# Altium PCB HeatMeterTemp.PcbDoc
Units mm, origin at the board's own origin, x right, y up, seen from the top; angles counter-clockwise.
Board outline 51.56 x 33.02 mm, 2 copper layers (Top Layer, Bottom Layer), stack 0.979 mm thick; 60 components, 38 nets, 163 pads, 77 vias.
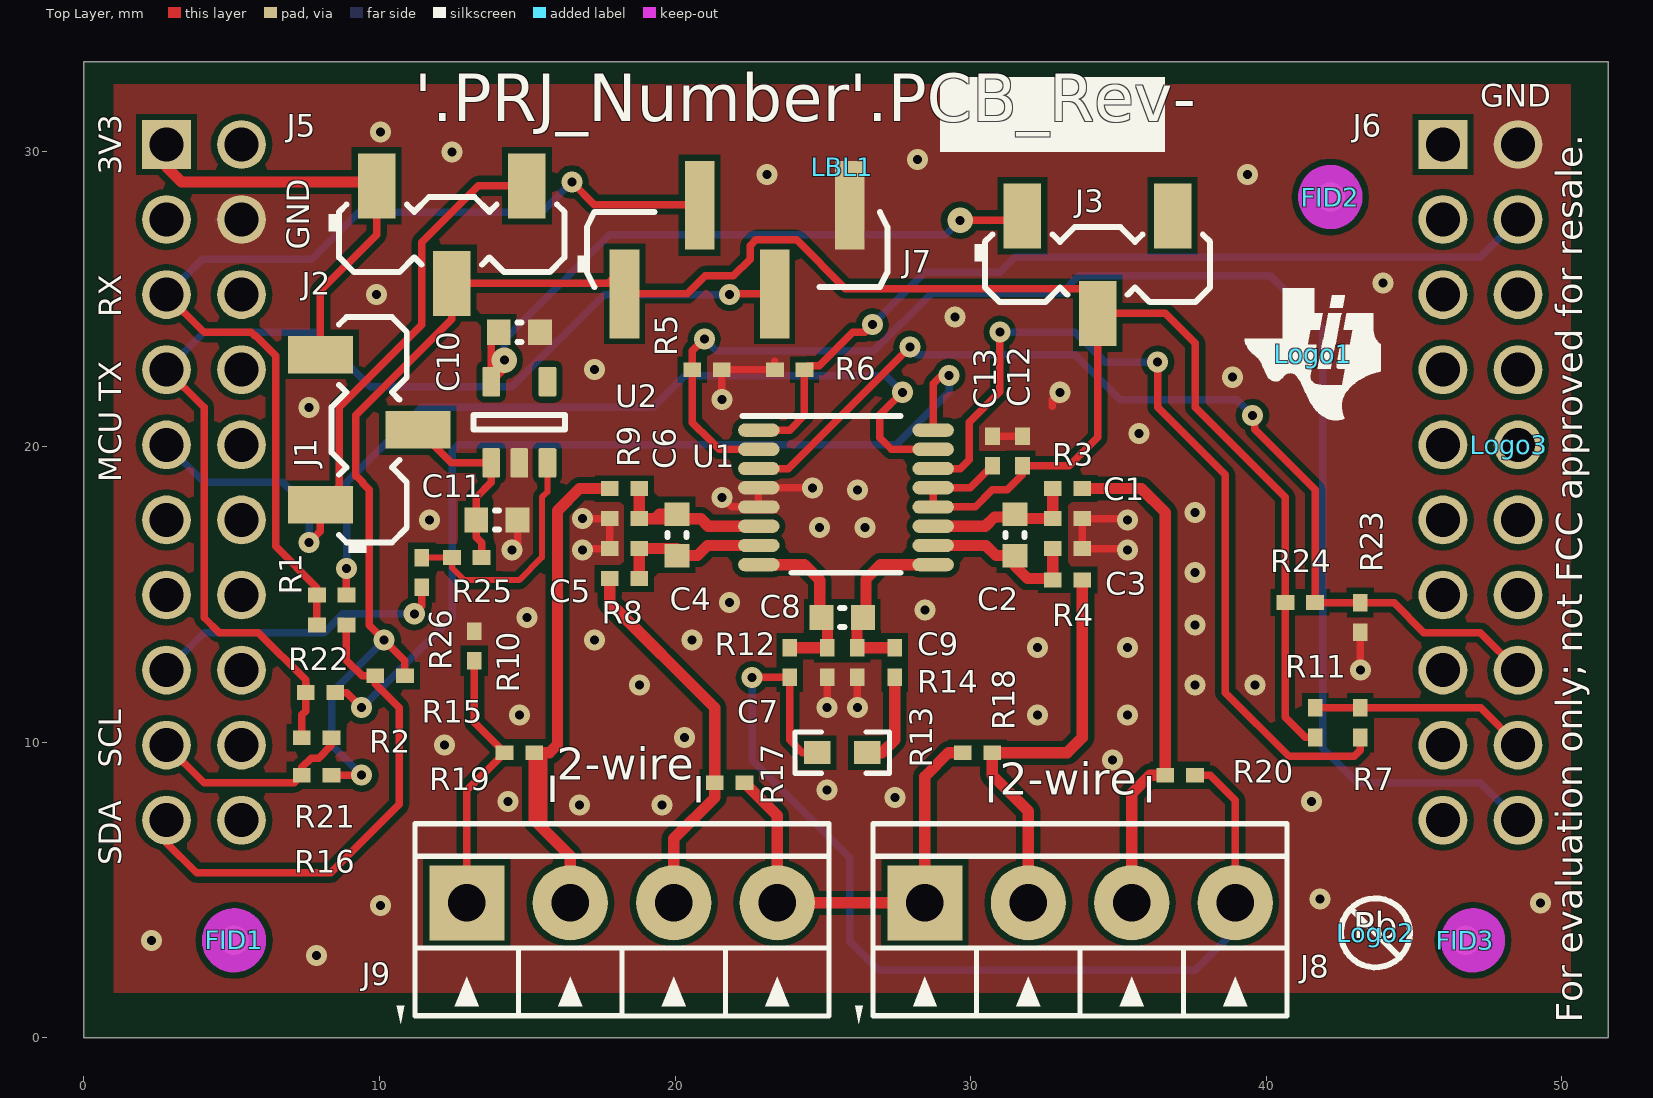
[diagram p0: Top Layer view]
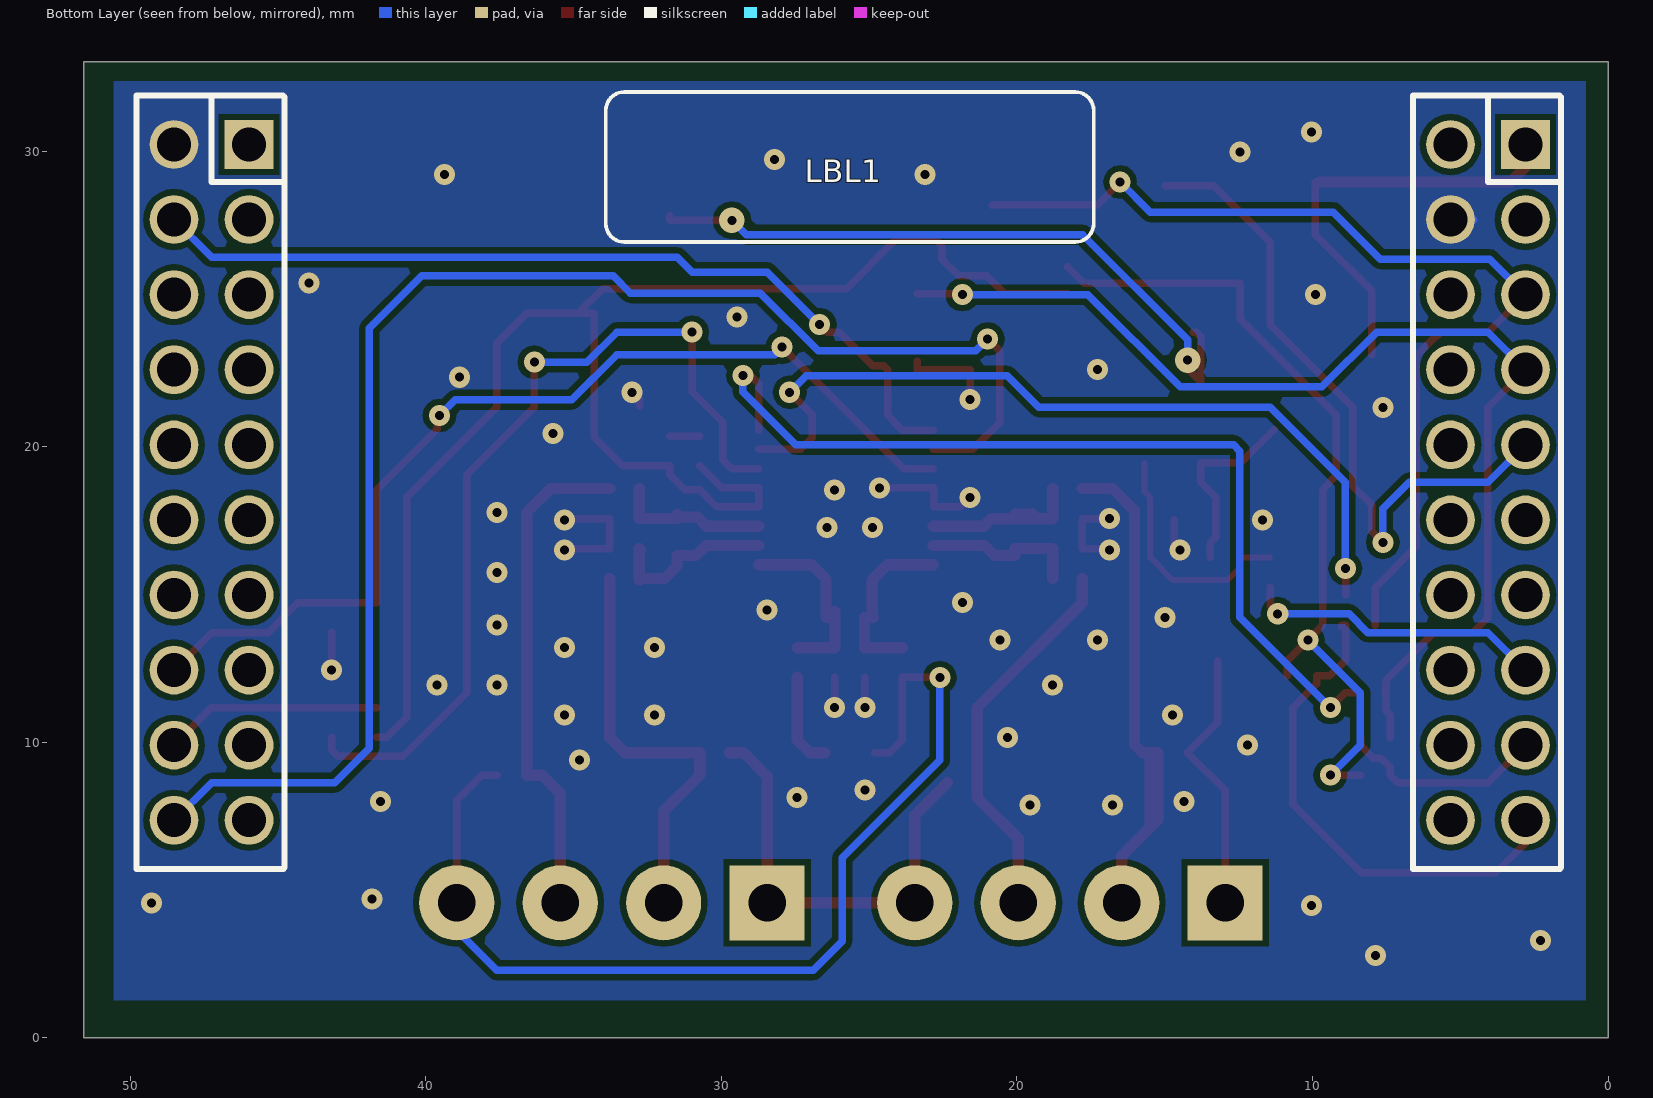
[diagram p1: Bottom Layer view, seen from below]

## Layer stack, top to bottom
Top Solder: solder mask 0.0102, Solder Resist, Dk 3.5
Top Layer: signal copper 0.0356
Dielectric1: core 0.908, FR-4, Dk 4.8
Bottom Layer: signal copper 0.0356
Bottom Solder: solder mask 0.0102, Solder Resist, Dk 3.5

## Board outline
0,0 51.562,0 51.562,33.02 0,33.02

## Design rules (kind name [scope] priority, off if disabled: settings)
AcuteAngle [All] p1: minimum=4.50000000000000E+0001 checktracksonly=FALSE
AssemblyTestPointUsage [All] p1: valid=2
BoardOutlineClearance BoardOutlineClearance_MountingHoles [OnCopper and InComponentClass('Mounting Holes')] p1: gap=1.016 ignorepadtopadclearanceinfootprint=FALSE except(0.762: Arc-OutlineEdge Track-OutlineEdge SMDPad-OutlineEdge)
BoardOutlineClearance BoardOutlineClearance_Poly [OnCopper and IsPoly] p2: gap=0.635 ignorepadtopadclearanceinfootprint=FALSE
BoardOutlineClearance [OnCopper and Not InComponentClass('Logo') and not InComponentClass('FiducialMark') and not InRegion(1000,500,4000,800) and not InPoly] p3: gap=1.905 ignorepadtopadclearanceinfootprint=FALSE
Clearance Clearance_Keepouts [((IsTrack Or IsArc) And Not InPoly) And IsFree and IsKeepOut vs ((IsTrack Or IsArc) And Not InPoly) And IsFree and IsKeepOut] p1: gap=0 ignorepadtopadclearanceinfootprint=FALSE
Clearance Clearance_Poly [InPolygon] p2: gap=0.203 ignorepadtopadclearanceinfootprint=FALSE except(0: Arc-Hole Track-Hole SMDPad-Hole THPad-Hole Via-Hole Fill-Hole Poly-Hole Region-Hole Text-Hole)
Clearance [All] p3: gap=0.2 ignorepadtopadclearanceinfootprint=FALSE except(0: Arc-Hole Track-Hole SMDPad-Hole THPad-Hole Via-Hole Fill-Hole Poly-Hole Region-Hole Text-Hole; 0.15: Arc-Via Track-Via SMDPad-Via THPad-Via Via-Via)
ComponentClearance ComponentClearance_MountingHoles_FiducialMarks [InComponentClass('Mounting Holes') vs InComponentClass('FiducialMark')] p1: gap=1.27 collisioncheckmode=3 verticalgap=0.254 showdistances=FALSE
ComponentClearance ComponentClearance_Shunt [InComponentClass('Header') vs InComponentClass('Shunt')] p2: gap=0 collisioncheckmode=3 verticalgap=0 showdistances=FALSE
ComponentClearance ComponentClearance_Logo [InComponentClass('Logo')] p3: gap=1.27 collisioncheckmode=3 verticalgap=0.254 showdistances=FALSE
ComponentClearance ComponentClearance_ScrewToNut [(HasFootprint('NY PMS 440 0025 PH')) vs (HasFootprint('Keystone_1902C'))] p4: gap=0.127 collisioncheckmode=3 verticalgap=0.254 showdistances=FALSE
ComponentClearance ComponentClearance_MountingHoles [InComponentClass('Mounting Holes')] p5: gap=6.35 collisioncheckmode=3 verticalgap=2540 showdistances=FALSE
ComponentClearance ComponentClearance_SmallPassives [HasFootprint('0201*') or HasFootprint('0402*') or HasFootprint('0508') or HasFootprint('0603*') or HasFootprint('0612') or HasFootprint('0805*') or HasFootprint('0815*') or HasFootprint('0830*') or HasFootprint('1206*') or HasFootprint('1210*') or HasFootprint('1808*') or HasFootprint('1812*') or HasFootprint('1825*') or HasFootprint('2010*') or HasFootprint('2220*') or HasFootprint('2225*') or HasFootprint('2512*') or HasFootprint('2728*') or HasFootprint('3518*') vs HasFootprint('0201*') or HasFootprint('0402*') or HasFootprint('0508') or HasFootprint('0603*') or HasFootprint('0612') or HasFootprint('0805*') or HasFootprint('0815*') or HasFootprint('0830*') or HasFootprint('1206*') or HasFootprint('1210*') or HasFootprint('1808*') or HasFootprint('1812*') or HasFootprint('1825*') or HasFootprint('2010*') or HasFootprint('2220*') or HasFootprint('2225*') or HasFootprint('2512*') or HasFootprint('2728*') or HasFootprint('3518*')] p6: gap=0.38 collisioncheckmode=3 verticalgap=0.254 showdistances=FALSE
ComponentClearance ComponentClearance_THtoSMT [IsThruComponent vs IsSMTComponent] p7: gap=1.016 collisioncheckmode=3 verticalgap=0.762 showdistances=FALSE
ComponentClearance ComponentClearance_THtoTH [IsThruComponent vs IsThruComponent] p8: gap=0.762 collisioncheckmode=3 verticalgap=0.762 showdistances=FALSE
ComponentClearance [All] p9: gap=0.762 collisioncheckmode=3 verticalgap=0.254 showdistances=FALSE
DiffPairsRouting [All] p1: maxlimit=2.54 minlimit=0.254 mostfreqgap=0.254 toplayer_minwidth=0.381 toplayer_maxwidth=0.381 toplayer_prefwidth=0.381 bottomlayer_minwidth=0.381 bottomlayer_maxwidth=0.381 bottomlayer_prefwidth=0.381 maxuncoupledlength=25.4
FabricationTestPointUsage TestPointUsage [All] p1: valid=2 allowmultiple=FALSE
FabricationTestpoint Testpoint [All] p1: side=3 testpointundercomponent=TRUE minsize=1.016 maxsize=2.54 preferedsize=1.524 minholesize=0 maxholesize=1.016 preferedholesize=0.813 testpointgrid=0.025 allowsidetop=TRUE allowsidebottom=TRUE usegrid=TRUE gridtolerance=0
FanoutControl Fanout_LCC [IsLCC] p1: bgadir=Out bgaviamode=Centered fanoutstyle=Auto fanoutdirection=Alternating viagrid=0.025 // Fanout_LCC (Default Rule)
FanoutControl Fanout_BGA [IsBGA] p2: bgadir=Out bgaviamode=Centered fanoutstyle=Auto fanoutdirection=Alternating viagrid=0.025 // Fanout_BGA (Default Rule)
FanoutControl Fanout_Default [All] p4: bgadir=Out bgaviamode=Centered fanoutstyle=Auto fanoutdirection=Alternating viagrid=0.025 // Fanout_Default (Default Rule)
FanoutControl Fanout_Small [(CompPinCount < 5)] p5: bgadir=Out bgaviamode=Centered fanoutstyle=Auto fanoutdirection=OutThenIn viagrid=0.025 // Fanout_Small (Default Rule)
HoleSize [All] p1: absolutevalues=TRUE maxlimit=6.375 minlimit=0.2 maxpercent=80.000 minpercent=20.000
MinimumAnnularRing MinimumAnnularRing_ThermalPadVias [IsVia and InAnyComponent] p1: minimumring=0.15
MinimumAnnularRing [All] p2: minimumring=0.203
MinimumSolderMaskSliver MinimumSolderMaskSliver_Logo [InComponentClass('Logo') vs InComponentClass('Logo')] p1: minsoldermaskwidth=0.018
MinimumSolderMaskSliver [All] p2: minsoldermaskwidth=0.1
PlaneClearance [All] p1: clearance=0.2
PlaneConnect [All] p1: planeconnectstyle=Direct reliefexpansion=0.254 reliefentries=4 reliefconductorwidth=0.254 reliefairgap=0.254
PolygonConnect [All] p1: connectstyle=Direct reliefconductorwidth=0.254 reliefentries=4 polygonreliefangle="90 Angle" airgapwidth=0.254
RoutingVias ThermalPadVias [IsVia and InAnyComponent] p1: holewidth=0.2 width=0.5 viastyle="Through Hole" minholewidth=0.2 minwidth=0.5 maxholewidth=0.33 maxwidth=0.6
RoutingVias [All] p2: holewidth=0.305 width=0.864 viastyle="Through Hole" minholewidth=0.2 minwidth=0.711 maxholewidth=1.016 maxwidth=1.651
SilkToBoardRegionClearance [Not ((IsComment or IsDesignator) And (Hide <> 'False')) and not InRegion(1000,500,4000,800)] p1:
SilkToSilkClearance SilkToSilkClearance_Pb-FreeLogo [(HasFootprint('Pb-Free_Overlay_Medium') OR HasFootprint('Pb-Free_Overlay_Small')) vs (HasFootprint('Pb-Free_Overlay_Medium') OR HasFootprint('Pb-Free_Overlay_Small'))] p1: silktosilkclearance=0
SilkToSilkClearance [All] p2: silktosilkclearance=0.102
SilkToSolderMaskClearance SilkToComponentPadClearance [(IsPad or IsFill or IsRegion) and InAnycomponent] p1: minsilkscreentomaskgap=0.127 clearancetoexposedcopper=TRUE
SilkToSolderMaskClearance "Silk to Solder Mask Opening" [All] p2: minsilkscreentomaskgap=0.102 clearancetoexposedcopper=FALSE
SolderMaskExpansion [All] p1: expansion=0.05
Width [All] p1: maxlimit=2.54 minlimit=0.152 preferedwidth=0.254 checkconnectedcopper=TRUE
14 further rules are at their usual default settings.

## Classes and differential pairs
component class Logo: Logo1
component class HeatMeterTemp_Hardware: FID1 FID2 FID3 LBL1 Logo1 Logo2 Logo3 ZZ1 ZZ2 ZZ3 ZZ4
component class FiducialMark: FID1 FID2 FID3
component class AssemblyNote: ZZ1 ZZ2 ZZ3 ZZ4
component class Label: LBL1
component class RTD_ADS122U04: C1 C2 C3 C4 C5 C6 C7 C8 C9 C10 C11 C12 C13 J1 J2 J3 J5 J6 J7 J8 J9 J14 R1 R2 R3 R4 R5 R6 R7 R8 R9 R10 R11 R12 R13 R14 R15 R16 R17 R18 R19 R20 R21 R22 R23 R24 R25 R26 U1 U2
component class Header: J1 J2 J3 J7
differential pair SensRTD2: +SensRTD2_P -SensRTD2_N
differential pair SensRTD1: +SensRTD1_P -SensRTD1_N
differential pair ADC_In1: +ADC_In1_P -ADC_In1_N
differential pair ADC_In2: +ADC_In2_P -ADC_In2_N
differential pair ADC_Ref: +ADC_Ref_P -ADC_Ref_N

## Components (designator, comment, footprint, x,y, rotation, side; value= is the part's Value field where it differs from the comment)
C1 "GCM155R71H472KA37D" 0402L 33.274,17.572 r180 top value=4700pF
C2 "GCM188R71H104KA57D" 0603L 31.496,17.018 r270 top value=0.1uF
C3 "GCM155R71H472KA37D" 0402L 33.274,16.556 r0 top value=4700pF
C4 "GCM188R71H104KA57D" 0603L 20.066,17.018 r90 top value=0.1uF
C5 "GCM155R71H472KA37D" 0402L 18.288,16.556 r0 top value=4700pF
C6 "GCM155R71H472KA37D" 0402L 18.288,17.572 r180 top value=4700pF
C7 "GCM155R71H472KA37D" 0402L 25.146,12.7 r90 top value=4700pF
C8 "GCM188R71H104KA57D" 0603L 25.654,14.224 r0 top value=0.1uF
C9 "GCM155R71H472KA37D" 0402L 26.162,12.7 r270 top value=4700pF
C10 "885012206026" 0603L 14.732,23.876 r0 top value=1uF
C11 "885012206026" 0603L 13.97,17.526 r0 top value=1uF
C12 "GRM155R71C104JA88D" 0402L 31.75,19.858 r270 top value=0.1uF
C13 "GRM155R71C104JA88D" 0402L 30.734,19.858 r270 top value=0.1uF
FID1 "Fiducial" Fiducial10-20#1 5.08,3.302 r0 top
FID2 "Fiducial" Fiducial10-20#1 42.164,28.448 r0 top
FID3 "Fiducial" Fiducial10-20#2 46.99,3.302 r0 top
J1 "M20-8770342" Harwin_M20-87703 9.652,20.574 r90 top locked
J2 "M20-8770342" Harwin_M20-87703 12.446,27.178 r0 top
J3 "M20-8770342" Harwin_M20-87703 34.29,26.162 r0 top
J5 "SSW-110-23-F-D" CONN_SSW-110-23-F-D 4.064,18.796 r90 top locked
J6 "SSW-110-23-F-D" CONN_SSW-110-23-F-D 47.244,18.796 r90 top locked
J7 "61000418221" Wurth_61000418221 22.098,26.67 r90 top
J8 "ED555/4DS" TERM_BLK_ED555-4DS 28.448,4.572 r0 top locked
J9 "ED555/4DS" TERM_BLK_ED555-4DS 12.954,4.572 r0 top locked
LBL1 "Size: 0.65\" x 0.20 \"" Label_650x200 25.654,29.464 r180 top
Logo1 "Texas Instruments" TI_Symbol_Overlay_Small 41.571,23.13 r0 top
Logo2 "Pb-Free Symbol" Pb-Free_Overlay_Small 43.688,3.556 r0 top
Logo3 "FCC disclaimer" FCC_disclaimer 48.197,20.066 r90 top
R1 "CRCW040247R0JNED" 0402L 8.382,14.986 r0 top value=47
R2 "CRCW040247R0JNED" 0402L 8.002,11.684 r0 top value=47
R3 "CRCW0402100RFKED" 0402L 33.274,18.588 r0 top value=100
R4 "CRCW0402100RFKED" 0402L 33.274,15.494 r0 top value=100
R5 "CRCW04020000Z0ED" 0402L 21.082,22.606 r180 top value=0
R6 "CRCW04020000Z0ED" 0402L 23.876,22.606 r0 top value=0
R7 "CRCW040247R0JNED" 0402L 43.18,10.668 r270 top value=47
R8 "CRCW0402100RFKED" 0402L 18.288,15.54 r0 top value=100
R9 "CRCW0402100RFKED" 0402L 18.288,18.588 r0 top value=100
R10 "CRCW04020000Z0ED" 0402L 13.208,13.259 r270 top value=0
R11 "CRCW04024K70JNED" 0402L 41.656,10.668 r90 top value=4.7k
R12 "CRCW0402100RFKED" 0402L 23.876,12.7 r270 top value=100
R13 "Y16362K00000F9R" VSMP_0603 25.654,9.652 r180 top value=2.00k
R14 "CRCW0402100RFKED" 0402L 27.432,12.7 r270 top value=100
R15 "CRCW04024K70JNED" 0402L 10.359,12.256 r0 top value=4.7k
R16 "CRCW04024K70JNED" 0402L 7.874,8.89 r0 top value=4.7k
R17 "CRCW04020000Z0ED" 0402L 21.844,8.636 r0 top value=0
R18 "CRCW04020000Z0ED" 0402L 30.226,9.652 r180 top value=0
R19 "CRCW04020000Z0ED" 0402L 14.732,9.652 r0 top value=0
R20 "CRCW04020000Z0ED" 0402L 37.084,8.89 r180 top value=0
R21 "CRCW04020000Z0ED" 0402L 7.874,10.16 r180 top value=0
R22 "CRCW04020000Z0ED" 0402L 8.382,13.97 r0 top value=0
R23 "CRCW04020000Z0ED" 0402L 43.18,14.224 r270 top value=0
R24 "CRCW04024K70JNED" 0402L 41.148,14.732 r180 top value=4.7k
R25 "CRCW04020000Z0ED" 0402L 12.954,16.256 r180 top value=0
R26 "CRCW04020000Z0ED" 0402L 11.43,15.748 r270 top value=0
U1 "ADS122U04IPW" PW0016A_N 25.781,18.288 r0 top locked
U2 "LP5907MFX-2.8/NOPB" DBV0005A_N 14.732,20.828 r90 top locked
ZZ1 "This Assembly Note is for PCB labels only" AssemblyNoteLabel 4.699,100.025 r0 top
ZZ2 "These assemblies are ESD sensitive, ESD precautions shall be observed." AssemblyNote 4.699,97.259 r0 top
ZZ3 "These assemblies must be clean and free from flux and all contaminants. Use of no clean flux is not acceptable." AssemblyNote 4.699,95.01 r0 top
ZZ4 "These assemblies must comply with workmanship standards IPC-A-610 Class 2, unless otherwise specified." AssemblyNote 4.699,92.761 r0 top

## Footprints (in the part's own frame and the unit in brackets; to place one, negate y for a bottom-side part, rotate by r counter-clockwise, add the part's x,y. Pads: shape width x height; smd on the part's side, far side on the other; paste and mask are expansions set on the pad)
0402L [mm] "0402 from SM-752 data"
  rect 0.6x0.5 smd: 1(-0.5,0) 2(0.5,0)
  body extent -0.55,-0.3 0.55,0.3, height 0.6
0603L [mm] "0603 from SM-752 data"
  rect 0.8x0.85 smd: 1(-0.7,0) 2(0.7,0)
  silkscreen extent -0.07,-0.33 0.07,0.33, body extent -0.87,-0.47 0.87,0.47, height 1
AssemblyNote [mm] "Assembly Note"
AssemblyNoteLabel [mm] "Assembly Note for PCB Labels"
CONN_SSW-110-23-F-D [mm] "SAMTEC"
  rect 1.65x1.65 hole 1.15: 1(11.43,1.27)
  round 1.65 hole 1.15: 2(11.43,-1.27) 3(8.89,1.27) 4(8.89,-1.27) 5(6.35,1.27) 6(6.35,-1.27) 7(3.81,1.27) 8(3.81,-1.27) 9(1.27,1.27) 10(1.27,-1.27) 11(-1.27,1.27) 12(-1.27,-1.27) 13(-3.81,1.27) 14(-3.81,-1.27) 15(-6.35,1.27) 16(-6.35,-1.27) 17(-8.89,1.27) 18(-8.89,-1.27) 19(-11.43,1.27) 20(-11.43,-1.27)
  body extent -13,-2.54 13,2.51, height 8.59
DBV0005A_N [mm] "SOT23, 5-Leads, Body 2.9x1.6mm, Pitch 0.95mm, Lead Span 2.8mm, IPC Medium Density"
  rrect17% 1x0.6 smd: 1(-1.375,0.95) 2(-1.375,0) 3(-1.375,-0.95) 4(1.375,-0.95) 5(1.375,0.95)
  silkscreen extent -0.25,-1.55 0.25,1.55, body extent -1.42,-1.46 1.42,1.46, height 1.09
FCC_disclaimer [mm]
Fiducial10-20#1 [mm]
  round 1 smd mask+0.5: 1(0,0)
  Top Layer keep-out circle w1.178: c0,0 r0.5
Fiducial10-20#2 [mm]
  round 1 smd mask+0.5: 1(-0.254,0)
  Top Layer keep-out circle w1.178: c0,0 r0.5
Harwin_M20-87703 [mm] "Header, 2.54mm, 3x1, SMT"
  rect 1.27x2.2 smd: 1(-2.54,1.65) 2(0,-1.65) 3(2.54,1.65)
  silkscreen extent -4.17,-1.27 3.81,1.27, body extent -3.81,-2.54 3.81,2.54, height 9.93
Label_650x200 [mm] "Thermal Transfer Label"
  body extent -8.26,-2.54 8.26,2.54, height 0.03
Pb-Free_Overlay_Small [mm]
  silkscreen extent -1.16,-1.17 1.17,1.17
PW0016A_N [mm] "TSOP, 16-Leads, Body 5x4.4mm, Pitch 0.65mm, IPC Medium Density"
  oval 1.4x0.45 smd: 1(-2.95,2.275) 2(-2.95,1.625) 3(-2.95,0.975) 4(-2.95,0.325) 5(-2.95,-0.325) 6(-2.95,-0.975) 7(-2.95,-1.625) 8(-2.95,-2.275) 9(2.95,-2.275) 10(2.95,-1.625) 11(2.95,-0.975) 12(2.95,-0.325) 13(2.95,0.325) 14(2.95,0.975) 15(2.95,1.625) 16(2.95,2.275)
  silkscreen extent -3.5,-2.55 1.85,2.75, body extent -3.21,-2.5 3.21,2.5, height 1
TERM_BLK_ED555-4DS [mm]
  rect 2.54x2.54 hole 1.27: 1(0,0)
  round 2.54 hole 1.27: 2(3.5,0) 3(7,0) 4(10.5,0)
  silkscreen extent -2.36,-4.09 12.25,2.67, body extent -1.75,-3.8 12.25,2.7, height 8.2
TI_Symbol_Overlay_Small [mm]
  silkscreen extent -2.3,-2.23 2.3,2.24
VSMP_0603 [mm] "Recommended by Vishay"
  rect 0.905x0.78 smd: 1(-0.843,0) 2(0.843,0)
  silkscreen extent -1.6,-0.7 1.6,0.7, body extent -0.86,-0.47 0.86,0.47, height 0.64
Wurth_61000418221 [mm] "Header, 2.54mm, 4x1, SMT"
  rect 3x1 smd: 1(-1.5,3.81) 2(1.5,1.27) 3(-1.5,-1.27) 4(1.5,-3.81)
  silkscreen extent -1.27,-5.08 1.27,5.4, body extent -2.5,-5.08 2.5,5.08, height 9.29

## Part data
C1 C3 C5 C6 C7 C9: "CAP, CERM, 4700 pF, 50 V,+/- 10%, X7R, AEC-Q200 Grade 1, 0402", Cap_Case=0402, Manufacturer=MuRata, Supplier Part Number 1=490-4915-1-ND, TempCo=X7R, Tolerance_%=10, Value2=50V, ValueDisplayed=4700pF
C2 C4 C8: "CAP, CERM, 0.1 µF, 50 V,+/- 10%, X7R, 0603", Cap_Case=0603, Manufacturer=MuRata, Supplier Part Number 1=490-4779-1-ND, TempCo=X7R, Tolerance_%=10, Value1="0.02 ohm", Value2=50V, ValueDisplayed=0.1µF
C10 C11: "CAP, CERM, 1 µF, 10 V,+/- 10%, X7R, 0603", Cap_Case=0603, Manufacturer="Wurth Elektronik", Supplier Part Number 1=732-7945-1-ND, TempCo=X7R, Tolerance_%=10, Value2=10V, ValueDisplayed=1µF
C12 C13: "CAP, CERM, 0.1 µF, 16 V,+/- 5%, X7R, 0402", Cap_Case=0402, Manufacturer=MuRata, Supplier Part Number 1=490-6327-1-ND, TempCo=X7R, Tolerance_%=5, Value2=16V, ValueDisplayed=0.1µF
FID1 FID2 FID3: "Fiducial mark.  There is nothing to buy or mount.", Manufacturer=N/A
J1 J2 J3: "Header, 2.54mm, 3x1, Gold, SMT", Color=Black, Current_A=3, Manufacturer=Harwin, Supplier Part Number 1=952-1951-ND
J5 J6: "Connector, Receptacle, 100mil, 10x2, Gold plated, TH", Manufacturer=Samtec
J7: "Header, 2.54mm, 4x1, Gold, SMT", Color=Black, Manufacturer="Wurth Elektronik", Supplier Part Number 1=732-5365-ND
J8 J9: "Terminal Block, 3.5mm Pitch, 4x1, TH", Color=Grey, Current_A=6, Manufacturer="On-Shore Technology", Supplier Part Number 1=ED1516-ND, Voltage_V=150
LBL1: library part THT-14-423-10, "Thermal Transfer Printable Labels, 0.650\" W x 0.200\" H - 10,000 per roll", Alternate Manufacturer=-, Manufacturer=Brady, Supplier Part Number 1=2065596
Logo1: library part TI_Logo, "Texas Instrument Corporate Signature"
Logo2: library part Pb-Free
Logo3: library part FCC_disclaimer, "FCC_disclaimer"
R1 R2 R7: "RES, 47, 5%, 0.063 W, 0402", Manufacturer=Vishay-Dale, Power_W=0.063, Supplier Part Number 1=541-47JCT-ND, TempCo="200 ppm/C", Tolerance_%=5, Value1=5%, Value2=0.063W, Value_Code=47R0, ValueDisplayed=47
R3 R4 R8 R9 R12 R14: "RES, 100, 1%, 0.063 W, 0402", Manufacturer=Vishay-Dale, Power_W=0.063, Supplier Part Number 1=541-100LCT-ND, TempCo="100 ppm/C", Tolerance_%=1, Value1=1%, Value2=0.063W, Value_Code=100R, ValueDisplayed=100
R5 R6 R10 R17 R18 R19 R20 R21 R22 R23 R25 R26: "RES, 0, 5%, 0.063 W, 0402", Manufacturer=Vishay-Dale, Power_W=0.063, Supplier Part Number 1=541-0.0JCT-ND, TempCo="200 ppm/C", Tolerance_%=5, Value1=5%, Value2=0.063W, Value_Code=0000, ValueDisplayed=0
R11 R15 R16 R24: "RES, 4.7 k, 5%, 0.063 W, 0402", Manufacturer=Vishay-Dale, Power_W=0.063, Supplier Part Number 1=541-4.7KJCT-ND, TempCo="200 ppm/C", Tolerance_%=5, Value1=5%, Value2=0.063W, Value_Code=4k70, ValueDisplayed=4.7k
R13: "RES, 2.00 k, 1%, 0.1 W, 0603, +/- 0.2 ppm/K", Manufacturer="Vishay Foil Resistors", Power_W=0.1, Supplier Part Number 1=Y16362K00000F9R-ND, TempCo="0.2 ppm/C", Tolerance_%=1, Value1=1%, Value2=0.1W, Value_Code=2k00, ValueDisplayed="2.00k +/- 0.2 ppm/K"
U1: "24-Bit, 4-Channel, 2-kSPS, Delta-Sigma ADC with UART Interface, PW0016A (TSSOP-16)", Alternate Manufacturer="Texas Instruments"
U2: library part CMP-0066015-1, "250-mA Ultra-Low-Noise, Low-IQ LDO, DBV0005A (SOT-23-5)", Alternate Manufacturer="Texas Instruments"
ZZ1: library part AssemblyNoteLabel, Alternate Manufacturer=-
ZZ2 ZZ3 ZZ4: library part AssemblyNote, Alternate Manufacturer=-

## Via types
v1: diameter 0.711, hole 0.305, Top Layer to Bottom Layer, 74 vias
v2: diameter 0.864, hole 0.305, Top Layer to Bottom Layer, 2 vias
v3: diameter 0.711, hole 0.305, Top Layer to Bottom Layer, tented top, 1 vias

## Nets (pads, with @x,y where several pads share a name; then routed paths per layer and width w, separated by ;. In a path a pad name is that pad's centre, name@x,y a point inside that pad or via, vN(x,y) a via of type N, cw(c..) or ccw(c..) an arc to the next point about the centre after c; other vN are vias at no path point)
3V3: J1.3 J2.1 J5.1 | length 14.7
  Top Layer w0.254: J1.3 8.002,25.274 9.906,27.178 J2.1 9.906,28.956 J2.1@9.778,28.956
  Top Layer w0.381: J5.1 2.794,29.464 3.302,28.956 J2.1@9.778,28.956
ADC_In1_N: C2.2 C3.1 R4.1 U1.10 | length 6.8
  Top Layer w0.381: U1.10 30.509,16.663 30.854,16.318 C2.2 31.496,15.964 31.92,15.54 R4.1@32.774,15.54 ; R4.1 R4.1@32.774,15.54 ; R4.1@32.774,15.54 32.774,16.518 32.736,16.518 C3.1 R4.1@32.774,15.54
ADC_In1_P: C1.2 C2.1 R3.1 U1.11 | length 5.4
  Top Layer w0.381: U1.11 30.491,17.313 30.805,17.628 31.432,17.628 C2.1@31.488,17.572 ; C2.1 31.496,17.564 C2.1@31.488,17.572 ; R3.1 32.774,18.059 C1.2 C2.1@31.488,17.572
ADC_In2_N: C4.2 C6.1 R9.2 U1.6 | length 6.5
  Top Layer w0.381: R9.2 C6.1 19.329,17.572 19.475,17.718 C4.2 ; C6.1@18.796,17.564 20.872,17.564 21.123,17.313 U1.6
ADC_In2_P: C4.1 C5.2 R8.2 U1.7 | length 5.4
  Top Layer w0.381: R8.2 C5.2 19.828,16.556 20.066,16.556 C4.1 20.756,16.318 21.101,16.663 U1.7
ADC_Ref_N: C7.2 C8.1 R12.1 U1.8 | length 6.1
  Top Layer w0.381: U1.8 24.373,16.013 24.892,15.494 24.892,14.262 24.854,14.224 C8.1 25.154,14.224 C7.2@25.154,13.208 ; R12.1 C7.2
ADC_Ref_P: C8.2 C9.1 R14.1 U1.9 | length 6.7
  Top Layer w0.381: C9.1@26.154,13.208 26.154,14.416 26.354,14.416 C8.2 26.454,14.224 26.454,15.522 26.945,16.013 U1.9 ; C9.1 R14.1
ADS_RX: R2.2 U1.16 | length 31.5
  Top Layer w0.254: R2.2 8.89,11.684 v1(9.398,11.176) ; U1.16 28.731,22.127 29.022,22.418 v1(29.267,22.418)
  Bottom Layer w0.254: v1(9.398,11.176) 12.454,14.232 12.454,19.85 12.67,20.066 27.474,20.066 29.267,21.859 v1(29.267,22.418)
ADS_TX: R1.2 U1.15 | length 28.2
  Top Layer w0.254: R1.2 8.882,15.756 8.89,15.764 v1(8.89,15.883) v1@8.89,16.002 ; v1(27.686,21.844) 27.68,21.844 26.924,21.088 26.924,20.309 27.32,19.913 U1.15
  Bottom Layer w0.254: v1@8.89,16.002 8.89,18.796 11.43,21.336 19.262,21.336 20.326,22.4 27.13,22.4 v1(27.686,21.844)
DRDY: R7.2 U1.14 | length 30
  Top Layer w0.254: U1.14 29.652,19.263 29.947,19.558 29.947,20.827 30.988,21.869 v1(30.988,23.876) ; v1(36.322,22.86) 36.322,21.336 38.608,19.05 38.608,11.684 40.767,9.525 42.977,9.525 43.18,9.728 R7.2
  Bottom Layer w0.254: v1(30.988,23.876) 33.528,23.876 34.544,22.86 v1(36.322,22.86)
EXT_VDD: J3.3
GND: C1.1 C3.2 C5.1 C6.2 C7.1 C9.2 C10.2 C11.2 C12.1 C13.1 J5.4 J6.2 J7.4 R5.1 R6.1 R10.1 R23.2 U1.4 U1.5 U2.2 | length 20.9
  Top Layer w0.254: v1(14.478,16.51) 14.67,16.702 C11.2 ; v1@16.81,17.572 v1(16.866,17.572) C6.2 17.788,17.039 C5.1 16.912,16.556 v1(16.866,16.51) ; v1(21.59,18.288) 21.915,17.963 22.809,17.963 22.809,18.613 U1.4 v1(24.646,18.613) ; v1@21.59,21.59 v1(21.582,21.598) R5.1 R6.1 23.376,22.893 ; v1(25.146,11.176) C7.1 ; v1(26.162,11.176) C9.2 ; C13.1 C12.1 ; 32.766,21.374 32.766,21.59 33.02,21.59 v1(33.02,21.844) ; v1(35.306,16.51) 35.26,16.556 C3.2 C1.1 35.006,17.572 35.052,17.526 v1(35.306,17.526) ; v1(43.18,12.446) R23.2
  Bottom Layer w0.254: J5.4@4.547,27.686 J5.4
  other v1: 7.874,2.794 2.286,3.302 10.033,4.484 49.276,4.572 41.822,4.699 16.764,7.874 19.558,7.874 14.351,8.001 41.529,8.001 27.432,8.128 25.146,8.382 34.798,9.398 12.192,9.906 20.32,10.16 14.732,10.922 32.258,10.922 35.306,10.922 18.796,11.938 37.592,11.938 39.624,11.938 32.258,13.208 35.306,13.208 17.272,13.462 20.574,13.462 37.592,13.97 14.986,14.224 28.448,14.478 21.844,14.732 37.592,15.748 24.892,17.272 26.416,17.272 11.684,17.526 37.592,17.78 26.162,18.542 35.687,20.447 7.62,21.336 38.862,22.352 17.272,22.606 29.464,24.384 9.906,25.146 23.114,29.21 39.37,29.21 28.194,29.718 12.446,29.972 10.033,30.646
  other v3: 43.942,25.542
GPIO0: J6.20 R5.2 U1.2 | length 50.3
  Top Layer w0.254: v1(20.988,23.647) 20.582,23.241 R5.2 20.582,20.82 21.168,20.234 21.173,20.234 21.494,19.913 U1.2
  Bottom Layer w0.254: v1(20.988,23.647) 21.395,23.241 26.721,23.241 28.677,25.197 33.071,25.197 33.655,25.781 40.132,25.781 41.908,24.005 41.908,9.804 43.076,8.636 47.244,8.636 J6.20
GPIO1: J6.4 R6.2 U1.1 | length 29.5
  Top Layer w0.254: U1.1 23.876,20.563 24.376,21.063 R6.2 24.506,22.736 24.877,22.736 26.017,23.876 26.416,23.876 v1(26.67,24.13)
  Bottom Layer w0.254: v1(26.67,24.13) 28.448,25.908 30.988,25.908 31.496,26.416 47.244,26.416 J6.4
GPIO2/_DRDY: J6.18 R7.1 R11.2 | length 7.4
  Top Layer w0.254: R11.2 R7.1 47.252,11.168 J6.18
I2C_SCL: J5.17 R16.1 R21.1 | length 7
  Top Layer w0.254: J5.17 4.064,8.636 7.12,8.636 R16.1 7.374,9.152 7.689,9.467 7.943,9.467 8.374,9.898 R21.1
I2C_SDA: J5.19 R15.1 R22.2 | length 17.3
  Top Layer w0.254: J5.19 2.794,6.604 3.81,5.588 8.357,5.588 10.668,7.899 10.668,11.176 9.859,11.985 R15.1 9.411,12.256 8.882,12.784 R22.2 9.011,13.97 9.011,13.908 R22.2@9.019,13.9
IDAC: J8.4 R12.2 R13.2 R20.1 | length 34.9
  Top Layer w0.254: v1(22.606,12.192) 22.614,12.2 R12.2 23.876,10.084 24.308,9.652 R13.2 ; R20.1 38.1,8.89 38.948,8.042 J8.4
  Bottom Layer w0.254: v1(22.606,12.192) 22.606,9.398 25.908,6.096 25.908,3.27 26.892,2.286 37.592,2.286 38.948,3.642 J8.4
LDO_2V8: C10.1 J3.1 U2.5 | length 22.8
  Top Layer w0.254: C10.1 13.932,23.876 13.782,23.726 U2.5 14.224,22.645 v2(14.224,22.928) ; v2(29.642,27.661) 31.75,27.661 J3.1
  Bottom Layer w0.254: v2(14.224,22.928) 14.224,23.622 17.78,27.178 29.159,27.178 v2(29.642,27.661)
LDO_ENBL: J5.15 R26.2 | length 10.3
  Top Layer w0.254: v1(11.176,14.351) 11.43,14.605 R26.2 R26.2@11.422,15.24
  Bottom Layer w0.254: J5.15 4.064,13.716 8.128,13.716 8.763,14.351 v1(11.176,14.351) v1@11.176,14.478
MCU_3V3: J1.1 J2.3 J5.9 | length 22.9
  Top Layer w0.254: v1(7.62,16.764) 8.002,17.146 J1.1 8.636,18.668 8.636,21.336 11.43,24.13 11.43,26.924 13.334,28.828 J2.3
  Bottom Layer w0.254: J5.9 4.064,18.796 6.724,18.796 7.62,17.9 v1(7.62,16.764)
NetC11_1: C11.1 J1.2 R25.1 U2.1 | length 6.4
  Top Layer w0.254: J1.2 12.423,19.453 U2.1 13.782,18.796 13.27,18.284 C11.1 13.27,16.939 13.454,16.755 R25.1
NetJ9_1: J9.1 R10.2 R19.1 | length 9.1
  Top Layer w0.254: J9.1 12.954,8.374 R19.1 13.208,10.676 R10.2
NetR13_1: R13.1 R14.2 | length 3.2
  Top Layer w0.381: R13.1 27,9.652 27.432,10.084 R14.2
NetR25_2: R25.2 R26.1 U2.3 | length 8.2
  Top Layer w0.203: R26.1 11.438,16.256 R25.2 12.454,15.906 12.874,15.486 14.724,15.486 15.494,16.256 15.494,18.288 15.682,18.476 U2.3
RESET: J6.16 R23.1 R24.1 U1.3 | length 35.1
  Top Layer w0.254: U1.3 23.835,19.263 v1(27.94,23.368) ; v1@39.612,21.058 39.612,20.586 39.624,20.574 ; 40.132,20.066 39.624,20.574 ; J6.16 47.244,13.716 45.331,13.716 44.323,14.724 R23.1 41.656,14.724 R24.1 41.648,18.55 39.624,20.574
  Bottom Layer w0.254: v1(27.94,23.368) 28.194,23.114 33.528,23.114 35.052,21.59 39.001,21.59 v1(39.534,21.058)
RTD_IDAC: J8.1 J9.4 R17.2 R18.2 | length 15.4
  Top Layer w0.381: R17.2 23.454,7.526 J9.4 J8.1 28.448,8.847 29.253,9.652 R18.2
SensRTD1_N: J9.2 R9.1 R19.2 | length 19.1
  Top Layer w0.381: J9.2 16.454,6.152 15.494,7.112 ; R9.1 16.771,18.588 16.018,17.835 16.018,9.922 15.748,9.652 R19.2 ; R19.2 15.232,7.374 15.494,7.112 ; R19.2 15.494,9.39 15.494,7.112
SensRTD1_P: J9.3 R8.1 R17.1 | length 13
  Top Layer w0.381: R8.1 17.788,14.724 21.344,11.168 R17.1 21.344,8.136 19.954,6.746 J9.3
SensRTD2_N: J8.2 R4.2 R18.1 | length 14.2
  Top Layer w0.381: J8.2 31.948,7.676 30.726,8.898 R18.1 33.266,9.652 33.774,10.16 R4.2 R4.2@33.774,15.54
SensRTD2_P: J8.3 R3.2 R20.2 | length 17.1
  Top Layer w0.381: R3.2 35.768,18.588 36.584,17.772 R20.2 36.068,8.89 35.448,8.27 J8.3
SPI_CLK: J5.13
SPI_CS1: J6.6
SPI_MISO: J6.14
SPI_MOSI: J6.12
UART_RX: J5.7 J7.3 R2.1 R21.2 | length 38.8
  Top Layer w0.254: J5.7 4.064,21.336 4.064,14.224 4.572,13.716 5.903,13.716 7.502,12.117 ; R21.2 7.374,10.93 7.502,11.058 R2.1 7.502,12.117 ; R2.1@7.534,11.686 7.502,12.117 ; v1(21.844,25.146) 21.868,25.17 J7.3
  Bottom Layer w0.254: J5.7 4.064,23.876 7.827,23.876 9.68,22.023 14.478,22.023 17.601,25.146 v1(21.844,25.146)
UART_TX: J5.5 J7.2 R1.1 R22.1 | length 34.2
  Top Layer w0.254: J5.5 4.064,23.876 5.657,23.876 5.775,23.758 5.811,23.758 6.486,23.083 6.486,16.628 7.882,15.232 R1.1 R22.1 ; v1(16.51,28.956) 17.272,28.194 20.804,28.194 J7.2
  Bottom Layer w0.254: J5.5 3.998,26.35 7.707,26.35 9.296,27.94 15.494,27.94 v1(16.51,28.956)
VCC: C12.2 C13.2 J2.2 J3.2 J7.1 R11.1 R15.2 R16.2 R24.2 U1.12 U1.13 | length 79.6
  Top Layer w0.254: R16.2 v1(9.398,8.89) ; R15.2 10.859,12.763 v1(10.16,13.462) 9.652,13.97 9.652,18.542 9.429,18.765 9.429,18.804 9.237,18.996 9.198,18.996 9.198,21.061 12.446,24.309 J2.2 17.729,25.527 J7.1@18.288,26.086 ; J7.1 20.405,25.17 21.013,25.779 21.969,25.779 22.541,26.351 22.541,26.805 22.733,26.997 24.108,26.997 25.756,25.349 34.012,25.349 J3.2@34.849,24.512 ; U1.12 30.155,17.963 30.734,18.542 31.242,18.542 31.75,19.05 C12.2 33.328,19.358 34.29,20.32 J3.2 J3.2@34.849,24.512 ; U1.12@28.731,17.967 U1.13 29.989,18.613 C13.2 ; R11.1 41.318,10.168 40.64,10.846 40.64,18.288 37.592,21.336 37.592,23.496 36.576,24.512 J3.2@34.849,24.512
  Bottom Layer w0.254: v1(9.398,8.89) 8.379,9.909 8.379,11.681 v1(10.16,13.462)
pads on no net: FID1.1 FID2.1 FID3.1 J5.2 J5.3 J5.6 J5.8 J5.10 J5.11 J5.12 J5.14 J5.16 J5.18 J5.20 J6.1 J6.3 J6.5 J6.7 J6.8 J6.9 J6.10 J6.11 J6.13 J6.15 J6.17 J6.19 U2.4

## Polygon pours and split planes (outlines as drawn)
GND on Bottom Layer "BOTTOM_LAYER_GND_P000" (solid, remove dead copper, pour order 0): 0.762,32.512 0.762,1.27 50.546,1.27 50.546,32.512
GND on Top Layer "TOP_LAYER_GND_P002" (solid, remove dead copper, pour order 2): 1.016,32.258 1.016,1.524 50.292,1.524 50.292,32.258

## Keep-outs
Keep-Out Layer:
  text ".Layer_Name" at 14.656,-21.806 h1.52

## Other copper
Top Layer:
  region: 43.688,12.446
  region: 43.688,12.446
  text ".Layer_Name" at 14.656,-21.806 h1.52
Bottom Layer:
  text ".Layer_Name" at 14.656,-21.806 h1.52

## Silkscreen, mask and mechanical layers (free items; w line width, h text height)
Top Overlay:
  region: 36.576,32.512 28.956,32.512 28.956,29.972 36.576,29.972
  text "GND" at 47.244,31.496 h0.76
  text "'.PRJ_Number'.PCB_Rev-" at 11.176,30.48 h2.75
  text "3V3" at 1.27,29.21 h0.76 r90
  text "GND" at 7.62,26.67 h0.76 r90
  text "RX" at 1.27,24.384 h0.76 r90
  text "3V3" at -65.786,18.796 h0.76 r90
  text "MCU TX" at 1.27,18.796 h0.76 r90
  text "SCL" at 1.27,9.144 h0.76 r90
  text "2-wire" at 16.002,8.382 h1.85
  text "2-wire" at 30.988,7.874 h1.85
  text "I" at 15.633,7.636 h1.85
  text "I" at 20.574,7.62 h1.85
  text "I" at 30.48,7.62 h1.85
  text "I" at 35.814,7.62 h1.85
  text "SDA" at 1.27,5.842 h0.76 r90
  text ".Layer_Name" at 14.656,-21.806 h1.52
Bottom Overlay:
  text ".Layer_Name" at 14.656,-21.806 h1.52
Top Paste:
  text ".Layer_Name" at 14.656,-21.806 h1.52
Bottom Paste:
  text ".Layer_Name" at 14.656,-21.806 h1.52
Top Solder:
  text ".Layer_Name" at 14.656,-21.806 h1.52
  text ".Layer_Name" at 14.656,-21.806 h1.52
Bottom Solder:
  text ".Layer_Name" at 14.656,-21.806 h1.52
Drill Guide:
  text ".Layer_Name" at 14.656,-21.806 h1.52
M1 Board Outline:
  the board outline again, w0.254
  text ".Layer_Name" at 14.656,-21.806 h1.52
M2 Board Dimensions:
  rectangle: 0,-6.985 3.175,-3.81
  rectangle: 3.175,-10.16 12.7,-6.985
  lines w0.178: 0,-6.985 25.4,-6.985 ; 3.175,-10.16 3.175,-3.81 ; 6.35,-10.16 6.35,-3.81 ; 12.7,-10.16 12.7,-3.81 ; 19.05,-10.16 19.05,-3.81 ; 0,-10.16 25.4,-10.16 25.4,-3.81 0,-3.81 0,-10.16
  text ".Layer_Name" at 14.656,-21.806 h1.52
M3 3D STEP Top:
  text ".Layer_Name" at 14.656,-21.806 h1.52
M4 3D STEP Bottom:
  text ".Layer_Name" at 14.656,-21.806 h1.52
M5 Assembly Top:
  lines w0.254: -7.417,-23.626 160.223,-23.626 ; -7.417,-18.462 160.274,-18.462 ; -7.417,-13.297 -7.417,-28.791 94.31,-28.791 160.274,-28.791 160.274,-13.297 -7.404,-13.297 -7.404,-28.791 32.614,-28.791 ; 55.194,-28.791 55.194,-13.297 ; 87.376,-18.462 87.376,-13.297 ; 108.712,-18.462 108.712,-13.297 ; 124.511,-28.956 124.511,-23.804
  text "COMPONENTS MARKED 'DNP' SHOULD NOT BE POPULATED." at 29.299,-8.09 h1.52
  text "ASSEMBLY VARIANT:" at 29.286,-11.024 h1.52
  text ".VariantName" at 55.601,-11.024 h1.52
  text "PCB VIEWED FROM TOP SIDE" at -5.804,-16.654 h1.52
  text "BOARD #:" at 57.099,-16.654 h1.52
  text ".PRJ_Number" at 70.955,-16.654 h1.52
  text "REV:" at 92.405,-16.654 h1.52
  text ".PCB_Rev" at 99.809,-16.654 h1.52
  text "SVN REV:" at 113.69,-16.654 h1.52
  text ".VersionControl_RevNumber" at 126.543,-16.654 h1.52
  text "TID #:" at 57.099,-21.819 h1.52
  text ".TID" at 70.955,-21.819 h1.52
  text "PLOT NAME =" at -5.804,-27.034 h1.52
  text ".plot_File_Name" at 14.656,-27.034 h1.52
  text "GENERATED    :" at 57.15,-27.034 h1.52
  text ".Print_Date" at 79.235,-27.034 h1.52
  text ".Print_Time" at 97.752,-27.034 h1.52
  text "TEXAS INSTRUMENTS" at 129.87,-27.034 h1.52
M6 Assembly Bottom:
  lines w0.254: -7.429,-18.474 160.261,-18.474 ; -7.379,-23.639 160.261,-23.639 ; 28.334,-28.969 28.334,-23.817 ; 44.133,-18.474 44.133,-13.31 ; 65.468,-18.474 65.468,-13.31 ; 97.65,-28.804 97.65,-13.31 ; 120.231,-28.804 160.249,-28.804 160.249,-13.31 -7.429,-13.31 -7.429,-28.804 58.534,-28.804 160.261,-28.804 160.261,-13.31
  text "COMPONENTS MARKED 'DNP' SHOULD NOT BE POPULATED." at 154.991,-8.077 h1.52
  text ".VariantName" at 128.473,-11.024 h1.52
  text "ASSEMBLY VARIANT:" at 154.864,-11.024 h1.52
  text ".VersionControl_RevNumber" at 26.302,-16.667 h1.52
  text "SVN REV:" at 39.154,-16.667 h1.52
  text ".PCB_Rev" at 53.035,-16.667 h1.52
  text "REV:" at 60.439,-16.667 h1.52
  text ".PRJ_Number" at 81.89,-16.667 h1.52
  text "BOARD #:" at 95.745,-16.667 h1.52
  text "PCB VIEWED FROM BOTTOM SIDE" at 158.648,-16.667 h1.52
  text ".TID" at 81.89,-21.831 h1.52
  text "TID #:" at 95.745,-21.831 h1.52
  text "TEXAS INSTRUMENTS" at 22.974,-27.047 h1.52
  text ".Print_Time" at 55.093,-27.047 h1.52
  text ".Print_Date" at 73.609,-27.047 h1.52
  text "GENERATED    :" at 95.694,-27.047 h1.52
  text ".plot_File_Name" at 138.189,-27.047 h1.52
  text "PLOT NAME =" at 158.648,-27.047 h1.52
M9 Title Sheet:
  drawing of 57 lines, arcs and shapes, not listed
  text "1" at 18.792,204.127 h1.78
  text "2" at 82.182,204.127 h1.78
  text "3" at 145.411,204.127 h1.78
  text "4" at 209.08,204.127 h1.78
  text "5" at 272.555,204.127 h1.78
  text "6" at 336.182,204.127 h1.78
  text "A" at -10.579,175.095 h1.78
  text "A" at 365.341,175.095 h1.78
  text "B" at -10.579,114.643 h1.78
  text "B" at 365.341,114.643 h1.78
  text "C" at -10.579,54.318 h1.78
  text "C" at 365.341,54.318 h1.78
  text "PROJECT TITLE:" at 288.125,7.048 h1.14
  text ".PRJ_Title" at 289.395,3.662 h1.78
  text "DESIGNED FOR:" at 288.125,-0.597 h1.14
  text ".PRJ_Customer" at 289.395,-4.153 h1.78
  text "D" at -10.579,-5.88 h1.78
  text "D" at 365.341,-5.88 h1.78
  text "FILE NAME:" at 288.125,-8.217 h1.14
  text ".PCB_File_Name_No_Path" at 289.395,-11.265 h1.78
  text "Texas Instruments (TI) and/or its licensors do not warrant the accuracy or completeness of this specification" at 161.9,-15.376 h1.14
  text "ENGINEER:" at 288.125,-15.583 h1.14
  text "LAYOUT BY:" at 326.352,-15.583 h1.14
  text "or any information contained therein. TI and/or its licensors do not warrant that this design will meet" at 160.757,-18.237 h1.14
  text ".PRJ_Engineer" at 289.395,-19.52 h1.78
  text ".PCB_Layout" at 327.635,-19.52 h1.78
  text "the specifications, will be suitable for your application or fit for any particular purpose, or will operate in" at 160.757,-21.099 h1.14
  text ".Layer_Name" at 14.656,-21.806 h1.52
  text "ALTIUM DESIGNER VERSION:" at 326.352,-23.457 h1.14
  text "an implementation. TI and/or its licensors do not warrant that the design is production worthy. You should" at 160.757,-23.961 h1.14
  text "completely validate and test your design implementation to confirm the system functionality for your application." at 161.9,-26.822 h1.14
  text ".print_Scale" at 289.395,-26.843 h1.78
  text ".Application_BuildNumber" at 327.635,-26.843 h1.78
  text "1" at 18.792,-32.093 h1.78
  text "2" at 82.182,-32.093 h1.78
  text "3" at 145.411,-32.093 h1.78
  text "4" at 209.08,-32.093 h1.78
  text "5" at 272.555,-32.093 h1.78
  text "6" at 336.182,-32.093 h1.78
M10 Fab Notes:
  drawing of 173 lines, arcs and shapes, not listed
  text "DESIGN INFORMATION" at 314.402,157.505 h1.52
  text "MIN. TRACK WIDTH:" at 298.03,152.933 h1.52
  text "8" at 325.874,152.933 h1.52
  text "MIL" at 329.805,152.933 h1.52
  text "MIN. CLEARANCE:" at 298.03,149.581 h1.52
  text "0.2" at 324.35,149.581 h1.52
  text "mm" at 329.805,149.581 h1.52
  text "MIN. VIA PAD SIZE:" at 298.03,146.228 h1.52
  text "24" at 325.113,146.228 h1.52
  text "MIL" at 329.805,146.228 h1.52
  text "0.05mm (2MIL)" at 315.683,142.628 h1.52
  text "MINIMUM ANNULAR RING" at 289.667,142.52 h1.52
  text "EXTERNAL" at 333.666,142.52 h1.52
  text "PER" at 294.747,139.522 h1.52
  text "IPC-D-275 CLASS 2 LEVEL C" at 300.335,139.522 h1.52
  text "MIL, HOLES" at 338.136,136.67 h1.52
  text "+/-" at 328.168,136.652 h1.52
  text "+/-" at 349.86,136.652 h1.52
  text "REGISTRATION TOLERANCES:" at 289.667,136.525 h1.52
  text "METAL" at 320.142,136.525 h1.52
  text "5" at 334.777,136.525 h1.52
  text "3" at 355.935,136.525 h1.52
  text "MIL" at 358.888,136.525 h1.52
  text "+/-" at 349.86,133.655 h1.52
  text "HOLE SIZE TOLERANCE (UNLESS OTHERWISE SPECIFIED):" at 289.667,133.528 h1.52
  text "3" at 355.935,133.528 h1.52
  text "MIL" at 358.888,133.528 h1.52
  text "MATERIAL:" at 287.768,128.208 h1.52
  text "FR-4 High Tg" at 312.824,124.643 h1.52
  text "FR-408" at 298.462,124.425 h1.52
  text "OTHER" at 336.257,124.425 h1.52
  text "X" at 308.889,124.333 h1.52
  text "62 MIL (1.6mm) +/-10%" at 306.592,120.292 h1.52
  text "THICKNESS:" at 289.667,120.184 h1.52
  text "X" at 303.337,120.184 h1.52
  text "OTHER" at 339.229,120.184 h1.52
  text "TOLERANCE:" at 289.667,116.17 h1.52
  text "X" at 310.986,116.17 h1.52
  text "ANSI IPC-6012 TYPE 3 CLASS 2" at 315.734,116.17 h1.52
  text "OTHER +/-" at 315.734,112.208 h1.52
  text "BOW & TWIST:" at 289.667,108.22 h1.52
  text "X" at 310.986,108.22 h1.52
  text "ANSI IPC-6012 TYPE 3 CLASS 2" at 315.734,108.22 h1.52
  text "OTHER +/-" at 315.734,104.194 h1.52
  text "DRILLING:" at 287.768,100.676 h1.52
  text "REFERENCE:" at 289.667,97.705 h1.52
  text "X" at 306.132,97.705 h1.52
  text "AS SHOWN" at 310.882,97.705 h1.52
  text "X" at 329.018,97.705 h1.52
  text "NC_DRILL FILES" at 332.498,97.705 h1.52
  text "PTH COPPER THICKNESS:" at 289.667,93.691 h1.52
  text "X" at 318.375,93.691 h1.52
  text "20-30 um" at 321.855,93.691 h1.52
  text "OTHER" at 340.067,93.691 h1.52
  text "BOARD FINISH:" at 287.768,89.653 h1.52
  text "SILKSCREEN:" at 291.711,86.656 h1.52
  text "X" at 315.81,86.656 h1.52
  text "TOP" at 319.01,86.656 h1.52
  text "X" at 328.764,86.656 h1.52
  text "BOTTOM" at 331.99,86.656 h1.52
  text "SILKSCREEN COLOR:" at 291.711,82.414 h1.52
  text "X" at 315.783,82.414 h1.52
  text "WHITE" at 319.01,82.414 h1.52
  text "OTHER" at 331.99,82.414 h1.52
  text "X" at 319.111,78.37 h1.52
  text "GREEN" at 322.338,78.37 h1.52
  text "OTHER" at 338.035,78.37 h1.52
  text "SOLDER RESIST COLOR:" at 291.711,78.096 h1.52
  text "X" at 319.111,74.052 h1.52
  text "MATTE" at 322.338,74.052 h1.52
  text "SEMI-GLOSS" at 338.023,74.036 h1.52
  text "IMMERSION GOLD (ENIG)" at 314.718,69.264 h1.52
  text "ENEPIG" at 348.691,69.18 h1.52
  text "SURFACE FINISH:" at 287.768,69.155 h1.52
  text "X" at 309.969,69.155 h1.52
  text "IMM. TIN/SILVER OR EQUIV" at 296.139,65.167 h1.52
  text "OTHER" at 332.498,65.167 h1.52
  text "ARRAY/PANEL:" at 287.768,60.621 h1.52
  text "CUT AND TRIM PER M1 BOARD OUTLINE" at 314.718,60.512 h1.52
  text "N.C. ROUTE" at 314.718,56.658 h1.52
  text "X" at 331.964,56.658 h1.52
  text "V. SCORE" at 336.714,56.658 h1.52
  text "CERTIFICATION:" at 287.768,53.178 h1.52
  text "MATERIALS AND WORKMANSHIP FOR ALL PCBS" at 306.183,53.178 h1.52
  text "TO MEET OR EXCEED THE REQUIREMENTS OF:" at 306.183,50.689 h1.52
  text "X" at 296.696,47.222 h1.52
  text "ANSI IPC-A-600F CLASS ->" at 300.227,47.222 h1.52
  text "X" at 341.859,47.222 h1.52
  text "2" at 344.88,47.222 h1.52
  text "1" at 336.879,47.184 h1.52
  text "3" at 353.872,47.184 h1.52
  text "X" at 317.373,43.171 h1.52
  text "RoHS" at 320.852,43.171 h1.52
  text "OTHER" at 337.22,43.171 h1.52
  text "PER ORDER" at 347.305,43.171 h1.52
  text "ALL BOARDS MUST MEET OR EXCEED UL94-V0 REQUIREMENTS." at 288.468,38.964 h1.52
  text "PCB MUST BEAR THE UL94V-0 UL REGISTERED MATERIAL ID NUMBER" at 288.468,35.916 h1.52
  text "ADDITIONAL REQUIREMENTS:" at 287.768,31.512 h1.52
  text "MICROSECTION:" at 289.667,28.591 h1.52
  text "YES" at 312.673,28.591 h1.52
  text "REQUIRED" at 334.555,24.625 h1.52
  text "BARE BOARD ELEC. TEST:" at 289.667,24.553 h1.52
  text "NONE" at 322.833,24.553 h1.52
  text "X" at 331.329,24.553 h1.52
  text "PER ORDER" at 349.592,24.553 h1.52
  text ".Layer_Name" at 14.656,-21.806 h1.52
M11 Gerber Information:
  lines w0.254: -7.417,-23.626 160.223,-23.626 ; -7.417,-18.462 160.274,-18.462 ; -7.417,-13.297 -7.417,-28.791 94.31,-28.791 160.274,-28.791 160.274,-13.297 -7.404,-13.297 -7.404,-28.791 32.614,-28.791 ; 55.194,-28.791 55.194,-13.297 ; 87.376,-18.462 87.376,-13.297 ; 108.712,-18.462 108.712,-13.297 ; 124.511,-28.956 124.511,-23.804
  text "ALL ARTWORK VIEWED FROM TOP SIDE" at -5.804,-16.654 h1.52
  text "BOARD #:" at 57.099,-16.654 h1.52
  text ".PRJ_Number" at 70.955,-16.654 h1.52
  text "REV:" at 92.405,-16.654 h1.52
  text ".PCB_Rev" at 99.809,-16.654 h1.52
  text "SVN REV:" at 113.69,-16.654 h1.52
  text ".VersionControl_RevNumber" at 126.543,-16.654 h1.52
  text "LAYER NAME =" at -5.804,-21.806 h1.52
  text "TID #:" at 57.099,-21.819 h1.52
  text ".TID" at 70.955,-21.819 h1.52
  text "PLOT NAME =" at -5.804,-27.034 h1.52
  text ".plot_File_Name" at 14.656,-27.034 h1.52
  text "GENERATED    :" at 57.15,-27.034 h1.52
  text ".Print_Date" at 79.235,-27.034 h1.52
  text ".Print_Time" at 97.752,-27.034 h1.52
  text "TEXAS INSTRUMENTS" at 129.87,-27.034 h1.52
M12 Stackup:
  drawing of 319 lines, arcs and shapes, not listed
  text "Layer" at 171.226,197.866 h1.52
  text "Name" at 181.638,197.866 h1.52
  text "Material" at 205.254,197.866 h1.52
  text "Thickness" at 227.092,197.866 h1.52
  text "Constant" at 243.598,197.866 h1.52
  text "Board Layer Stack" at 258.072,197.866 h1.52
  text "1" at 171.226,194.818 h1.52
  text "Top Overlay" at 181.638,194.818 h1.52
  text "2" at 171.226,191.77 h1.52
  text "Top Solder" at 181.638,191.77 h1.52
  text "Solder Resist" at 205.254,191.77 h1.52
  text "0.40mil" at 227.092,191.77 h1.52
  text "3.5" at 243.598,191.77 h1.52
  text "3" at 171.226,188.722 h1.52
  text "Top Layer" at 181.638,188.722 h1.52
  text "Copper" at 205.254,188.722 h1.52
  text "1.40mil" at 227.092,188.722 h1.52
  text "4" at 171.226,185.674 h1.52
  text "Dielectric1" at 181.638,185.674 h1.52
  text "FR-4" at 205.254,185.674 h1.52
  text "35.75mil" at 227.092,185.674 h1.52
  text "4.8" at 243.598,185.674 h1.52
  text "5" at 171.226,182.626 h1.52
  text "Bottom Layer" at 181.638,182.626 h1.52
  text "Copper" at 205.254,182.626 h1.52
  text "1.40mil" at 227.092,182.626 h1.52
  text "6" at 171.226,179.578 h1.52
  text "Bottom Solder" at 181.638,179.578 h1.52
  text "Solder Resist" at 205.254,179.578 h1.52
  text "0.40mil" at 227.092,179.578 h1.52
  text "3.5" at 243.598,179.578 h1.52
  text "7" at 171.226,176.53 h1.52
  text "Bottom Overlay" at 181.638,176.53 h1.52
  text ".Layer_Name" at 14.656,-21.806 h1.52
M13 Component Bodies Top:
  text ".Layer_Name" at 14.656,-21.806 h1.52
M14 Component Bodies Bottom:
  text ".Layer_Name" at 14.656,-21.806 h1.52
M15 Courtyards Top:
  text ".Layer_Name" at 14.656,-21.806 h1.52
M16 Courtyards Bottom:
  text ".Layer_Name" at 14.656,-21.806 h1.52
Drill Drawing:
  lines w0.254: 63.415,1.842 64.536,1.842 64.536,2.963 63.415,2.963 63.415,1.842 ; 63.415,5.486 64.536,5.486 63.975,4.365 63.415,5.486 ; 63.415,7.168 63.695,7.168 63.975,6.887 64.256,7.168 64.536,7.168 64.256,7.448 64.536,7.728 64.256,7.728 63.975,8.009 63.695,7.728 63.415,7.728 63.695,7.448 63.415,7.168
  lines w0.305: 62.382,1.085 141.407,1.085 ; 62.382,8.653 141.407,8.653 ; 70.396,-1.438 70.396,11.176 ; 78.45,-1.438 78.45,11.176 ; 94.24,-1.438 94.24,11.176 ; 100.442,-1.438 100.442,11.176 ; 109.592,-1.438 109.592,11.176 ; 127.587,-1.438 127.587,11.176 ; 62.382,-1.438 141.407,-1.438 141.407,11.176 62.382,11.176 62.382,-1.438
  text "Symbol" at 63.896,9.41 h1.83
  text "Quantity" at 71.153,9.41 h1.83
  text "Finished Hole Size" at 79.207,9.41 h1.83
  text "Plated" at 94.996,9.41 h1.83
  text "Hole Type" at 101.199,9.41 h1.83
  text "Drill Layer Pair" at 110.349,9.41 h1.83
  text "Hole Tolerance" at 128.344,9.41 h1.83
  text "77" at 71.153,6.887 h1.52
  text "12.00mil (0.305mm)" at 79.207,6.887 h1.52
  text "PTH" at 94.996,6.887 h1.52
  text "Round" at 101.199,6.887 h1.52
  text "Top Layer - Bottom Layer" at 110.349,6.887 h1.52
  text "40" at 71.153,4.365 h1.52
  text "45.28mil (1.150mm)" at 79.207,4.365 h1.52
  text "PTH" at 94.996,4.365 h1.52
  text "Round" at 101.199,4.365 h1.52
  text "Top Layer - Bottom Layer" at 110.349,4.365 h1.52
  text "8" at 71.153,1.842 h1.52
  text "50.00mil (1.270mm)" at 79.207,1.842 h1.52
  text "PTH" at 94.996,1.842 h1.52
  text "Round" at 101.199,1.842 h1.52
  text "Top Layer - Bottom Layer" at 110.349,1.842 h1.52
  text "125 Total" at 71.153,-0.681 h1.52
  text ".Layer_Name" at 14.656,-21.806 h1.52
M17 Embedded Cavity:
  text ".Layer_Name" at 14.656,-21.806 h1.52
M18 Embedded Assembly:
  text ".Layer_Name" at 14.656,-21.806 h1.52
M19 Embedded Keepout:
  text ".Layer_Name" at 14.656,-21.806 h1.52

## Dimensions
0,-10.16 to 25.4,-10.16 on M2 Board Dimensions
0,0 to 0,33.02 on M2 Board Dimensions
0,0 to 51.562,0 on M2 Board Dimensions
